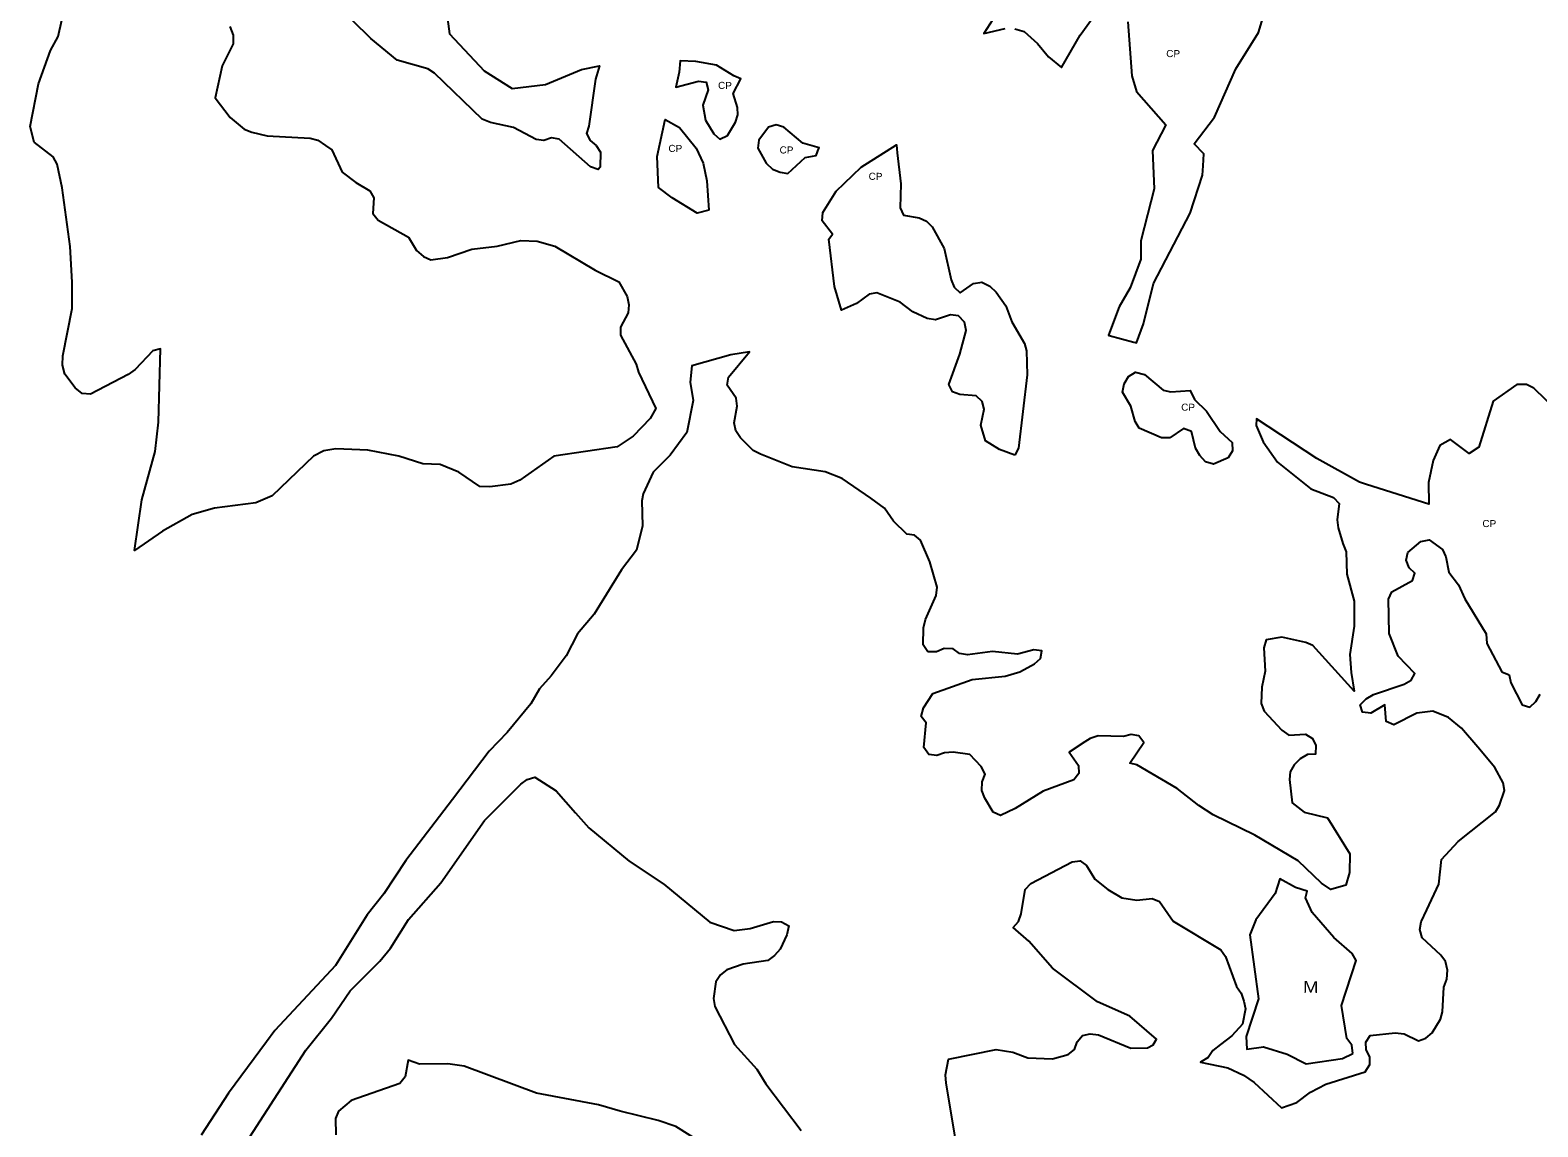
# Model space of a CAD drawing. Extents: x 713589 to 726391, y 7177764 to 7191819.
# Drawn here: x 719506 to 720865, y 7185112 to 7186101 of the extents above; entities that cross this region are included whole.
import ezdxf
from ezdxf.enums import TextEntityAlignment as Align

# ---------------------------------------------------------------- set-up
doc = ezdxf.new("R2010")
doc.units = 0
doc.header["$LTSCALE"] = 2.6
doc.layers.add('63', color=7, linetype='Continuous', lineweight=25)

msp = doc.modelspace()

# ---------------------------------------------------------------- linework, layer by layer
at = {"layer": '63'}
for points in [[(719879.01, 7186133.81), (719883.65, 7186097.68), (719915.12, 7186064.54), (719940.31, 7186048.62), (719970.46, 7186052.26), (720002.94, 7186065.51), (720019.2, 7186068.89), (720015.58, 7186057.07), (720009.55, 7186014.62), (720007.33, 7186007.97), (720010.5, 7186001.63), (720016.2, 7185997.19), (720020, 7185991.17), (720019.77, 7185977.76), (720017.78, 7185975.65), (720010.81, 7185977.87), (719982.62, 7186002.9), (719975.65, 7186004.17), (719969, 7186001.64), (719962.03, 7186002.59), (719941.44, 7186013.36), (719920.85, 7186017.8), (719913.25, 7186020.97), (719870.17, 7186062.48), (719864.16, 7186066.28), (719836.6, 7186074.21), (719812.84, 7186093.53), (719796.69, 7186109.38)], [(720393.64, 7186102.42), (720402.02, 7186099.92), (720414.13, 7186089.12), (720424.07, 7186077.15), (720435.68, 7186067.49), (720452.58, 7186096.54), (720474.69, 7186126.89)], [(720495.47, 7186108.74), (720499.09, 7186059.92), (720503.37, 7186045.74), (720529.93, 7186015.85), (720525.64, 7186007.58), (720517.88, 7185992.62), (720519.19, 7185957.99), (720507.31, 7185911.15), (720507.31, 7185894.66), (720497.73, 7185868.93), (720487.84, 7185851.78), (720478.04, 7185826.17), (720478.79, 7185825.83), (720501, 7185819.86), (720503.29, 7185819.3), (720509.6, 7185836.27), (720518.85, 7185872.88), (720551.68, 7185936.05), (720563.07, 7185970.52), (720563.5, 7185978.78), (720564.06, 7185989.65), (720555.28, 7185998.67), (720573.63, 7186022.63), (720593.1, 7186066.17), (720613.56, 7186099.16), (720621.15, 7186124.88)], [(719685.49, 7186104.33), (719688.66, 7186096.72), (719688.66, 7186088.8), (719678.83, 7186068.85), (719672.49, 7186040.02), (719685.8, 7186022.28), (719698.46, 7186011.82), (719705.43, 7186009.29), (719719.37, 7186005.8), (719758.02, 7186003.89), (719764.99, 7186001.99), (719771.96, 7185997.24), (719777.66, 7185993.12), (719786.84, 7185973.16), (719799.2, 7185963.65), (719811.87, 7185956.36), (719815.67, 7185950.03), (719814.71, 7185935.77), (719819.46, 7185929.75), (719846.71, 7185914.54), (719853.99, 7185902.5), (719860.32, 7185897.12), (719866.98, 7185893.95), (719881.87, 7185896.16), (719904.04, 7185903.76), (719926.85, 7185906.29), (719948.08, 7185911.36), (719962.97, 7185911.04), (719978.81, 7185906.28), (720015.23, 7185884.73), (720036.46, 7185874.28), (720044.06, 7185860.97), (720045.64, 7185853.37), (720045, 7185846.4), (720038.03, 7185833.41), (720038.03, 7185826.12), (720052.28, 7185800.15), (720054.18, 7185792.86), (720069.83, 7185759.93), (720064.76, 7185750.93), (720049.48, 7185734.97), (720035.08, 7185725.47), (719977.77, 7185717.05), (719947.11, 7185695.31), (719939.07, 7185691.89), (719920.27, 7185689.44), (719911.06, 7185689.64), (719892.16, 7185702.77), (719875.21, 7185709.43), (719859.83, 7185710.32), (719837.99, 7185716.98), (719810.07, 7185722.57), (719781.37, 7185723.65), (719770.5, 7185721.89), (719761.09, 7185717.19), (719723.86, 7185681.25), (719709.17, 7185674.98), (719671.85, 7185670.29), (719651.67, 7185664.51), (719624.92, 7185649.43), (719599.51, 7185632.15), (719606.29, 7185677.87), (719618.15, 7185721.41), (719621.29, 7185747.85), (719623.02, 7185813.77), (719616.06, 7185811.94), (719600.22, 7185795.16), (719593.89, 7185790.72), (719559.99, 7185772.99), (719552.38, 7185773.62), (719546.05, 7185778.69), (719536.86, 7185791.05), (719534.65, 7185798.97), (719534.97, 7185807.52), (719543.53, 7185850.29), (719543.53, 7185874.05), (719541.64, 7185906.04), (719534.36, 7185958.95), (719529.93, 7185980.17), (719526.44, 7185986.83), (719509.02, 7186000.13), (719505.54, 7186014.39), (719513.15, 7186052.72), (719523.93, 7186082.81), (719530.9, 7186095.48), (719534.07, 7186110.06)], [(720373.75, 7186110.74), (720365.66, 7186098.01), (720384.85, 7186102.65)], [(720315.17, 7185540.65), (720311.05, 7185546.98), (720311.37, 7185562.19), (720312.96, 7185569.79), (720322.78, 7185591.33), (720323.73, 7185598.94), (720317.09, 7185621.75), (720308.54, 7185641.39), (720303.15, 7185645.82), (720296.18, 7185646.78), (720284.15, 7185658.5), (720276.23, 7185670.22), (720263.88, 7185679.09), (720237.9, 7185696.84), (720222.7, 7185702.86), (720192.92, 7185707.62), (720164.41, 7185719.03), (720157.76, 7185722.2), (720146.36, 7185733.6), (720141.92, 7185739.94), (720140.66, 7185747.23), (720143.19, 7185762.11), (720142.24, 7185769.4), (720134.33, 7185781.12), (720135.28, 7185788.41), (720154.22, 7185810.99), (720137.54, 7185808.29), (720102.25, 7185798.4), (720100.92, 7185783.88), (720103.56, 7185767.39), (720097.95, 7185738.36), (720082.77, 7185717.91), (720067.59, 7185702.74), (720058.35, 7185683.28), (720057.33, 7185676.91), (720057.96, 7185654.42), (720052.57, 7185632.25), (720038.94, 7185614.51), (720014.23, 7185574.6), (719999.33, 7185556.86), (719988.88, 7185537.22), (719975.57, 7185519.17), (719964.8, 7185507.45), (719957.17, 7185493.93), (719935.64, 7185467.85), (719919.49, 7185451.07), (719886.53, 7185407.67), (719844.39, 7185352.56), (719824.43, 7185322.47), (719809.53, 7185303.46), (719781.01, 7185257.85), (719726.2, 7185199.25), (719718.79, 7185189.26), (719684.37, 7185142.87), (719659.66, 7185104.86)], [(720883.33, 7185757.36), (720861.89, 7185778.48), (720855.3, 7185781.78), (720846.39, 7185781.78), (720824.95, 7185766.61), (720812.07, 7185725.05), (720803.5, 7185719.44), (720786.68, 7185731.98), (720777.11, 7185726.7), (720770.84, 7185713.18), (720766.88, 7185693.39), (720767.01, 7185673.96), (720710.91, 7185691.54), (720704.45, 7185693.56), (720666.01, 7185715.11), (720611.78, 7185750.74), (720611.41, 7185744.61), (720617.74, 7185730.04), (720630.72, 7185711.66), (720660.5, 7185687.58)], [(720660.5, 7185687.58), (720681.09, 7185679.97), (720686.16, 7185674.27), (720684.25, 7185659.7), (720685.2, 7185652.41), (720689.63, 7185638.47), (720692.48, 7185630.87), (720693.11, 7185610.59), (720699.76, 7185586.52), (720699.76, 7185563.71), (720695.95, 7185538.36), (720696.9, 7185522.21), (720699.6, 7185505.35), (720662.37, 7185546.29), (720656.04, 7185549.14), (720634.5, 7185553.9), (720620.24, 7185551.37), (720618.34, 7185544.4), (720619.6, 7185523.17), (720616.43, 7185508.92), (720615.8, 7185494.03), (720618.65, 7185487.06), (720634.48, 7185469.95), (720640.82, 7185465.51), (720655.71, 7185466.46), (720662.04, 7185462.66), (720665.21, 7185456.32), (720664.89, 7185448.4), (720657.6, 7185448.09), (720650.95, 7185444.29), (720645.56, 7185438.9), (720642.08, 7185432.57), (720641.44, 7185425.6), (720643.66, 7185404.69), (720654.74, 7185396.13), (720675.82, 7185391.18), (720695.92, 7185358.74), (720695.6, 7185341.64), (720692.11, 7185330.23), (720678.65, 7185326.48), (720670.35, 7185332.16), (720649.2, 7185352.27), (720610.14, 7185375.49), (720572.58, 7185393.89), (720559.48, 7185402.12), (720540.16, 7185417.62), (720503.58, 7185438.81), (720497.41, 7185440.46), (720509.98, 7185458.88), (720505.55, 7185464.9), (720498.58, 7185466.17), (720491.61, 7185464.27), (720468.8, 7185464.91), (720461.51, 7185462.69), (720456.8, 7185459.58), (720442.82, 7185450.34), (720451.06, 7185438.3), (720451.37, 7185431.02), (720446.94, 7185425.31), (720419.37, 7185415.18), (720394.03, 7185399.35), (720380.72, 7185393.01), (720374.07, 7185396.18), (720366.47, 7185408.85), (720363.93, 7185415.82), (720364.25, 7185423.43), (720366.79, 7185430.4), (720363.31, 7185437.37), (720353.17, 7185448.14), (720337.96, 7185450.36), (720330.36, 7185449.73), (720323.39, 7185447.19), (720316.11, 7185448.15), (720311.67, 7185454.48), (720313.58, 7185476.66), (720309.14, 7185482.36), (720311.36, 7185490.28), (720319.6, 7185503.27), (720355.08, 7185515.61), (720384.86, 7185518.78), (720398.04, 7185522.67), (720398.8, 7185522.89), (720411.47, 7185529.86), (720416.86, 7185534.61), (720418.13, 7185541.58), (720410.84, 7185542.53), (720395.95, 7185538.73), (720373.46, 7185540.95), (720350.97, 7185538.11), (720343.68, 7185539.06), (720337.98, 7185543.5), (720330.06, 7185543.81), (720323.09, 7185540.65), (720315.17, 7185540.65)], [(720536.37, 7185297.79), (720579.48, 7185272.11), (720583.75, 7185266.19), (720593.62, 7185238.87), (720597.9, 7185232.95), (720600.2, 7185225.71), (720601.84, 7185218.8), (720598.88, 7185204.98), (720589.34, 7185194.45), (720579.22, 7185186.67), (720572.22, 7185181.29), (720567.94, 7185175.04), (720561.06, 7185170.78), (720585.86, 7185165.65), (720600.06, 7185159.18), (720609.59, 7185152.61), (720634.08, 7185129.75), (720648.05, 7185134.47), (720660.4, 7185143.65), (720674.03, 7185150.93), (720709.51, 7185162.02), (720713.94, 7185168.67), (720713.94, 7185175.64), (720710.46, 7185181.97), (720710.15, 7185188.94), (720714.27, 7185194.96), (720736.76, 7185197.17), (720744.68, 7185196.22), (720757.66, 7185189.88), (720764.32, 7185192.42), (720770.02, 7185197.17), (720777.63, 7185209.52), (720779.53, 7185216.17), (720780.48, 7185238.35), (720783.33, 7185245.64), (720783.97, 7185253.87), (720782.07, 7185261.47), (720777.95, 7185267.18), (720761.17, 7185283.02), (720758.95, 7185290.31), (720760.22, 7185297.28), (720765.28, 7185308.11), (720776.06, 7185331.17), (720778.6, 7185353.34), (720793.49, 7185369.81), (720827.08, 7185396.42), (720830.88, 7185402.44), (720835.32, 7185415.74), (720834.05, 7185422.71), (720826.45, 7185436.33), (720811.25, 7185454.71), (720796.68, 7185471.82), (720784.96, 7185481.64), (720770.71, 7185487.35), (720756.13, 7185485.45), (720735.54, 7185475), (720728.57, 7185477.85), (720727.31, 7185493.06), (720714.63, 7185485.46), (720707.35, 7185486.41), (720705.13, 7185493.06), (720708.09, 7185496.02), (720710.52, 7185498.45), (720717.17, 7185502.25), (720744.73, 7185511.43), (720751.07, 7185515.23), (720754.55, 7185521.25), (720739.35, 7185536.77), (720731.44, 7185557.37), (720730.81, 7185588.09), (720733.66, 7185594.75), (720752.35, 7185604.88), (720754.57, 7185611.53), (720749.19, 7185616.28), (720746.65, 7185623.25), (720748.24, 7185630.22), (720759.96, 7185640.04), (720767.25, 7185641.62), (720779.28, 7185633.07), (720782.45, 7185626.42), (720784.98, 7185612.48), (720793.85, 7185601.07), (720799.55, 7185588.4), (720818.78, 7185557.02), (720819.42, 7185548.06), (720833.01, 7185522.54), (720839.67, 7185519.89), (720841.13, 7185512.62), (720851.33, 7185492.87), (720858.24, 7185490.9), (720863.5, 7185495.83), (720867.45, 7185502.41)], [(719703.69, 7185103.59), (719754.07, 7185181.59), (719777.2, 7185210.33), (719794.32, 7185235.04), (719820.93, 7185261.96), (719830.44, 7185273.68), (719846.91, 7185299.34), (719876.06, 7185332.59), (719915.36, 7185388.66), (719947.99, 7185421.28), (719953.69, 7185425.72), (719960.66, 7185427.62), (719979.99, 7185415.26), (719997.45, 7185395.54), (720009.44, 7185381.99), (720045.87, 7185351.89)], [(720045.87, 7185351.89), (720077.23, 7185331.29), (720118.72, 7185297.07), (720140.58, 7185289.47), (720154.83, 7185291.36), (720176.06, 7185297.7), (720183.34, 7185297.38), (720189.68, 7185293.57), (720188.09, 7185285.66), (720182.07, 7185272.67), (720177, 7185266.97), (720170.98, 7185262.53), (720148.49, 7185259.05), (720133.92, 7185253.99), (720128.21, 7185249.55), (720124.09, 7185243.22), (720121.87, 7185228.33), (720123.14, 7185221.04), (720140.87, 7185186.83), (720160.83, 7185164.33), (720169.06, 7185151.34), (720201.05, 7185109.2)], [(720342.51, 7185087.22), (720331.67, 7185151.72), (720331.01, 7185159.29), (720333.97, 7185173.44), (720376.75, 7185182.31), (720391.89, 7185179.68), (720405.38, 7185174.74), (720427.76, 7185173.75), (720441.91, 7185177.69), (720447.5, 7185182.3), (720449.81, 7185189.21), (720454.75, 7185194.8), (720461.66, 7185196.45), (720469.23, 7185195.46), (720498.18, 7185183.28), (720513.32, 7185183.6), (720518.55, 7185186.35), (720521.47, 7185191.66), (720497.46, 7185212.19), (720468.18, 7185225.3), (720427.7, 7185255.62), (720406.43, 7185279.8), (720392.19, 7185292.23), (720396.85, 7185297.48), (720399.48, 7185304.39), (720403.11, 7185326.44), (720408.04, 7185331.71), (720445.23, 7185351.44), (720452.47, 7185352.43), (720458.39, 7185348.15), (720465.96, 7185335.64), (720477.48, 7185326.43), (720490.31, 7185318.86), (720503.8, 7185316.88), (720517.62, 7185318.19), (720524.2, 7185315.56), (720536.37, 7185297.79)], [(720144.49, 7185077.44), (720087.97, 7185112.76), (720072.05, 7185118.28), (720037.62, 7185126.66), (720018.23, 7185132.19), (719962.37, 7185142.83), (719897.04, 7185167.26), (719882.15, 7185169.22), (719856.78, 7185169.13), (719846.49, 7185172.61), (719843.92, 7185157.53), (719838.98, 7185151.61), (719795.21, 7185136.15), (719783.69, 7185126.61), (719781.06, 7185120.03), (719781.39, 7185105.22)]]:
    msp.add_lwpolyline(points, dxfattribs=at)
for points in [[(720134.37, 7186006.04), (720141.65, 7186018.08), (720143.87, 7186024.73), (720143.56, 7186031.39), (720139.76, 7186044.06), (720146.61, 7186057.23), (720140.14, 7186059.86), (720124.57, 7186069.47), (720106.01, 7186072.79), (720091.85, 7186073.58), (720090.98, 7186063.39), (720087.81, 7186049.77), (720108.4, 7186055.15), (720115.37, 7186054.2), (720116.95, 7186047.23), (720112.2, 7186033.61), (720114.73, 7186019.99), (720122.33, 7186007.63), (720127.71, 7186002.88)], [(720117.77, 7185938.92), (720107.22, 7185936.29), (720084.46, 7185949.82), (720072.26, 7185959.38), (720070.94, 7185987.09), (720078.32, 7186020.67), (720091.07, 7186013.48), (720106.24, 7185994.67), (720112.5, 7185981.15), (720115.8, 7185965.31)], [(720175.23, 7185975.94), (720181.88, 7185973.09), (720188.85, 7185971.82), (720204.69, 7185986.39), (720214.62, 7185988.05), (720217.03, 7185994.72), (720217.18, 7185994.94), (720202.47, 7185999.38), (720185.37, 7186013.64), (720178.4, 7186015.86), (720171.43, 7186013.64), (720162.88, 7186001.92), (720161.92, 7185994.63), (720169.53, 7185981.33)], [(720393.77, 7185718.04), (720379.83, 7185723.11), (720367.16, 7185731.03), (720363.04, 7185744.97), (720365.9, 7185759.54), (720364.31, 7185766.51), (720358.93, 7185771.58), (720344.04, 7185772.53), (720337.39, 7185775.07), (720334.22, 7185781.72), (720344.05, 7185808.96), (720349.75, 7185830.5), (720348.17, 7185837.79), (720342.79, 7185843.49), (720335.5, 7185844.45), (720322.19, 7185840.01), (720314.59, 7185841.28), (720301.6, 7185847.3), (720290.2, 7185855.86), (720269.29, 7185864.42), (720262.32, 7185863.15), (720250.92, 7185854.6), (720237.46, 7185848.58), (720230.91, 7185869.96), (720225.97, 7185912.84), (720229.18, 7185917.34), (720219.89, 7185929.37), (720220.52, 7185936.65), (720232.56, 7185955.97), (720255.06, 7185977.51), (720286.83, 7185997.66), (720287.64, 7185990.64), (720290.85, 7185962.62), (720290.22, 7185941.07), (720293.38, 7185934.42), (720307.32, 7185931.88), (720313.97, 7185929.03), (720319.04, 7185923.96), (720329.81, 7185904.32), (720336.14, 7185876.12), (720338.99, 7185869.47), (720344.37, 7185864.4), (720356.41, 7185872.64), (720364.02, 7185873.9), (720370.98, 7185870.42), (720376.69, 7185865.03), (720385.55, 7185852.67), (720390.94, 7185838.1), (720402.34, 7185818.77), (720404.24, 7185812.12), (720404.87, 7185790.26), (720396.94, 7185724.37)], [(720533.47, 7185733.53), (720525.87, 7185733.54), (720505.91, 7185742.41), (720502.11, 7185748.43), (720498.31, 7185762.05), (720490.71, 7185774.72), (720492.3, 7185782.33), (720496.1, 7185788.98), (720502.44, 7185792.78), (720510.67, 7185790.56), (720527.46, 7185776.62), (720534.43, 7185775.03), (720551.74, 7185776.25), (720555.65, 7185768.06), (720566.42, 7185757.6), (720578.77, 7185739.23), (720589.54, 7185729.41), (720589.86, 7185721.8), (720586.06, 7185715.47), (720572.75, 7185709.77), (720565.78, 7185711.99), (720560.4, 7185717.69), (720556.6, 7185724.34), (720553.12, 7185739.23), (720545.83, 7185742.09)], [(720698.42, 7185178.49), (720697.55, 7185185.99), (720692.99, 7185192.13), (720688.39, 7185221.75), (720701.56, 7185262.55), (720697.94, 7185268.8), (720681.49, 7185283.28), (720661.75, 7185305.66), (720655.83, 7185318.83), (720657.37, 7185324.99), (720646.81, 7185328.34), (720632.59, 7185335.99), (720628.52, 7185322.78), (720611.07, 7185299.09), (720605.48, 7185285.6), (720613.36, 7185228.01), (720602.17, 7185193.79), (720603.03, 7185182.53), (720617.96, 7185184.52), (720639.18, 7185177.87), (720656.29, 7185169.31), (720689.24, 7185174.06)]]:
    msp.add_lwpolyline(points, close=True, dxfattribs=at)

# ---------------------------------------------------------------- texts
for s, height, width, p in [('CP', 6.4, 1.05, (720536.42, 7186076.79)), ('CP', 6.4, 1.05, (720132.19, 7186048.09)), ('CP', 6.4, 1.05, (720087.41, 7185991.3)), ('CP', 6.4, 1.05, (720187.68, 7185989.91)), ('CP', 6.4, 1.05, (720267.98, 7185966.15)), ('CP', 6.4, 1.05, (720549.87, 7185758.01)), ('CP', 6.4, 1.05, (720821.56, 7185653.11)), ('M', 10.4, 1.2, (720660.5, 7185233.37))]:
    msp.add_text(s, height=height, rotation=359.062, dxfattribs=dict(at, width=width)).set_placement(p, align=Align.CENTER)

doc.saveas('drawing.dxf')
